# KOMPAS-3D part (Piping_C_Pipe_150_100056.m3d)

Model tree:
1. Plane XY
2. Plane ZX
3. Plane ZY
4. X Axis
5. Y Axis
6. Z Axis
7. Origin
8. Path  (labels: Тройник Dy 150; Труба Dy 150; Задвижка Dy 150)
9. Plane of section
10. Section of pipe
11. Pipe  (labels: C:\Program Files\ASCON\KOMPAS-3D V10\Sys\graphic.lyt; Труба Dy 150)
     Толщина стенки 1 = 1

Referenced files in C:\Program Files\ASCON\KOMPAS-3D V10\Libs\Piping\Models\Tanks\: Tanks.a3d
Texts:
  Pipe Dn 150
  Steel ASTM A295
  Three Point Plane
  Plane at Angle
  Line and Point Plane
  Axis through Two Vertices
  Axis of Feature
  Axis of Conical Surface
  Axis through Edge
  Приклеить элемент выдавливания
  Приклеить элемент вращения
  Приклеить кинематический элемент
  Приклеить элемент по сечениям
  Trim by Surface
  Trim by Sketch
  Feature with No History
  Intersection Axis of Two Planes
  Two Line Plane
  Line and Face Plane
  Bend by line
  Hole in sheet body
  Cut in sheet body
  Point in CM
  Linear Dimension from Line to Point
  Surface Finish Symbol
  Geometric Tolerance Symbol
  Текст на чертеже
  Линия-выноска #1
  Линия-выноска #2
  Линия-выноска #3
  Отклонения формы и база
  Марка координационной оси
  Марка/позиционное обозначение с линией-выноской
  Марка/позиционное обозначение на линии
  Марка/позиционное обозначение без линии-выноски
  Тройник Dy 150
  Труба Dy 150
  Задвижка Dy 150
